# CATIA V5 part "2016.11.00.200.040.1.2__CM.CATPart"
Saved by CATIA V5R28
Part number: 2016.11.00.200.040.1.2__CM
Property "id_number": "2016.11.00.200.040.1.2"
Publications: "Absolute Axis System", "driver", "slider", "base", "cam diagram"
Bounding box of the stored display mesh (mm): x -40 to 200, y -155 to 155, z 0 to 280
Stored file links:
  N:\B2\Normteile\K\2016\11-14\020\cm\2016.11.00.200.040.1.2__CM.CATPart
  H:\CAD_Startmodelle\Tests\fill-in_PRT-SL_TEMPLATE.xlsx
  H:\CAD_Startmodelle\V5-R24\R24_TEMPLATE_PRT_FIBRO_CAM_TECNOLOGIES_INDEX.xlsx
  H:\z_Einordnen\170511__Anfrage_TK_HN\170511__CC01_TKHN.CATPart
  N:\B2\Normteile\K\2016\9xxx\2016.9024.1705.001\Entwurf_\170511__CC01_TKHN.CATPart
  N:\B2\Normteile\K\2016\9xxx\2016.9024.1707.006\Konstruktion\2016.9024.1707.006__HP__CUSTOMIZED_CAM_CM.CATPart
  N:\B2\Normteile\K\2016\9xxx\2016.9024.1707.005\Konstruktion\2016.9024.1707.005__HP__CUSTOMIZED_CAM_CM.CATPart
  N:\B2\Normteile\K\2016\9xxx\2016.9024.1707.008\Konstruktion\2016.9024.1707.008__HP__CUSTOMIZED_CAM_CM.CATPart
  N:\B2\Normteile\K\2016\9xxx\2016.9024.1707.009\Konstruktion\2016.9024.1707.009__HP__CUSTOMIZED_CAM_CM.CATPart
  N:\B2\Normteile\K\2016\9xxx\2016.9024.1707.010\Konstruktion\2016.9024.1707.010__HP__CUSTOMIZED_CAM_CM.CATPart
  N:\B2\Normteile\K\2016\9xxx\2016.9024.1708.002\Konstruktion\2016.9024.1708.002__HP__CUSTOMIZED_CAM_CM.CATPart
  N:\B2\Normteile\K\2016\9xxx\2016.9024.1802.001\Konstruktion\2016.9024.1802.001__HP__CUSTOMIZED_CAM_CM.CATPart
  N:\B2\Normteile\K\2016\9xxx\2016.9024.1802.002\Konstruktion\2016.9024.1802.002__HP__CUSTOMIZED_CAM_CM.CATPart
  N:\B2\Normteile\K\2016\9xxx\2016.9024.1811.003\Konstruktion\2016.9024.1811.003__HP__CUSTOMIZED_CAM_CM.CATPart
  N:\B2\Normteile\K\2016\9xxx\2016.9015.1811.001\Konstruktion\am\2016.9015.1811.001__AM__FCC_HV_DMC_0125-00.CATPart
  N:\B2\Normteile\K\2016\9xxx\2016.9024.1811.009\Konstruktion\2016.9024.1811.009__HP__CUSTOMIZED_CAM_CM.CATPart
  N:\B2\Normteile\K\2016\9xxx\2016.9024.1911.002\Konstruktion\am\2016.9024.1911.002__AM__CUSTOMIZED_CAM_CM.CATPart
  N:\B2\Normteile\K\2016\9xxx\2016.9024.2002.006\Konstruktion\2016.9024.2002.006__AM.CATPart
  N:\B2\Normteile\K\2016\9xxx\2016.9024.2004.001\Konstruktion\2016.9024.2004.001__AM__FCC_HV_CAEC_0260-45.CATPart
  N:\B2\Normteile\K\2016\9xxx\2016.9024.2006.002\Konstruktion\2016.9024.2006.002__AM__FCC_HV_CAEC_0260-40.CATPart
  N:\B2\Normteile\K\2016\9xxx\2016.9024.2006.005\Konstruktion\am\2016.9024.2006.005__AM__CFCC_HV_AEPC_0080-65.CATPart
  N:\B2\Normteile\K\2016\9xxx\2016.9024.2006.004\Konstruktion\am\2016.9024.2006.004__AM__CFCC_HV_AEC_0210-35.CATPart
  N:\B2\Normteile\K\2016\9xxx\2016.9026.2006.001\Konstruktion\am\2016.9026.2006.001__AM__FCC_LV_CAEC_0180-40.CATPart
  N:\B2\Normteile\K\2016\9xxx\2016.9015.2007.001\Konstruktion\am\2016.9015.2007.001__AM__FCC_HV_CDMPC_0090-00.CATPart
  N:\B2\Normteile\K\2016\9xxx\2016.9024.2005.001\Konstruktion\am\2016.9024.2005.001__AM__CFCC_HV_AEPC_1400-70.CATPart
  N:\B2\Normteile\K\2016\9xxx\2016.9024.2007.004\Konstruktion\am\2016.9024.2007.004__AM__CFCC_HV_AEC_1250-80.CATPart
  N:\B2\Normteile\K\2016\11-14\005\2016.11.00.052.040.1.02__AS__DIE_MOUNT_CAM__W52_A0_S40.CATProduct
  N:\B2\Normteile\K\2016\11-14\015\2016.11.00.150.060.1.02__AS__DIE_MOUNT_CAM__W150_A0_S60.CATProduct
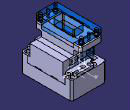
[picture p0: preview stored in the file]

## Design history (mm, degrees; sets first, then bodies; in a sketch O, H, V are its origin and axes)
Parameters
  group "process_parameters"
    modeltype = ""
    stocklist = ""
    id_number = "2016.11.00.200.040.1.2"
    id_number_rough_part = ""
    revision_index = ""
    revision_date = ""
    revision_description = ""
    category = ""
    material = ""
    manufacturing_information = ""
    standard = ""
  group "release_parameters_startmodel"
    sm_revision_index = "2016_00" {design table}
    sm_revision_date = "20.08.2016" {design table}
    sm_revision_name = "Meyer" {design table}
    sm_revision_description = "new part template FIBRO cam tecnologies" {design table}
AxisSystem1: origin (0, 0, 0), X (1, 0, 0), Y (0, 1, 0), Z (0, 0, 1)
Set1 "reference elements"
  Sketch1 "cam diagram" on ZX plane of AxisSystem1, origin (0, 0, 0), H (-1, 0, 0), V (0, 0, 1)
    line L1 (0, 0) -> (40, 0)
    line L2 (40, 0) -> (0, 40)
    point P2 (0, 40)
    line L3 (0, 40) -> (0, 0)
    length L1 = 40
    angle H L2 = 45
    horizontal: L1 H
    coincidence: P2 V
    vertical: L3 V
Body1 "finished_part" (main body)
  Body2 "rough_part"
  Add1 "rough_part": tool Body2
  Body3 "milling operations"
  Remove1 "milling operations": tool Body3
  Body4 "drilling operations"
  Remove2 "drilling operations": tool Body4
Body5 "driver"
  Solid1: solid without history
Body6 "slider"
  Solid2: solid without history
Body7 "base"
  Solid3: solid without history
Body8 "opened position"
  Body9 "slider"
    Body10 "slider"
      Solid4: linked copy from another document
    Assemble1: tool Body10
    Translate1: FirstPoint vertex [element of Sketch1 | element of Sketch1], SecondPoint vertex [element of Sketch1 | element of Sketch1], ToTransfor Assemble1
  Assemble2: tool Body9
  Body11 "driver"
    Body12 "driver"
      Solid5: linked copy from another document
    Assemble3: tool Body12
    Translate2: FirstPoint vertex [element of Sketch1 | element of Sketch1], SecondPoint vertex [element of Sketch1 | element of Sketch1], ToTransfor Assemble3
  Assemble4: tool Body11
